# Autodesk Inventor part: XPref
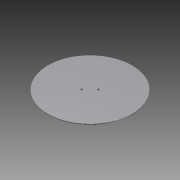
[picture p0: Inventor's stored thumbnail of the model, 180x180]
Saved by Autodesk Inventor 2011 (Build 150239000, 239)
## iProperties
Created: 2014-11
Part Number: XPref
Document SubType Name: Modeling
Designer: Evgeny
Density: 1 g/cm^3
Author: Evgeny
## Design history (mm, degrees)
sketch "Эскиз1"
  geometry: C1 r 60 at (0, 0); C2 r 1.5 at (6, 6); C3 r 1.5 at (-6, -6); 1 further point
  constraints: 3 centre point, 1 coincident
  dimensions: "d24" = 6 horizontal distance of C2.centre point (0, 0); "d25" = 3 diameter of C2; "d26" = 6 horizontal distance of C2.centre point (0, 0); "d27" = 120 diameter of C1; "d28" = 3 diameter of C3; "d29" = 6 horizontal distance of point (0, 0) C3.centre; "d30" = 6 horizontal distance of C3.centre point (0, 0)
extrude "Выдавливание2" new body sketch "Эскиз1" distance "d31" = 1; taper "d32" = 0 deg
node "Твердое тело2"
